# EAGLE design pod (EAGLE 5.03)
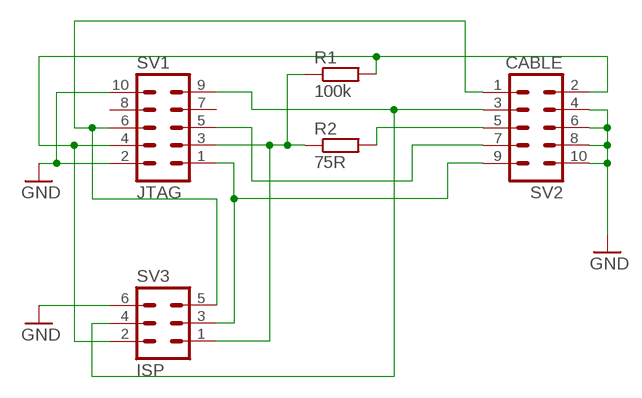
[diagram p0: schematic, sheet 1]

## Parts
R1  100k  R  [0207/10]
R2  75R  R  [0207/10]
SV1  JTAG  ML10L  [ML10L]
SV2  CABLE  ML10L  [ML10L]
SV3  ISP  ML6L  [ML6L]

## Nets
GND [supply]: SV1.2 SV1.10 SV2.4 SV2.6 SV2.8 SV2.10 SV3.6
N$1: R1.1 R2.1 SV1.3 SV3.1
N$2: R1.2 SV1.4 SV2.2 SV3.2
N$3: R2.2 SV2.5
N$4: SV1.6 SV2.1 SV3.5
N$5: SV1.9 SV2.3 SV3.4
N$6: SV1.5 SV2.7
N$7: SV1.1 SV2.9 SV3.3
Unconnected: SV1.7 SV1.8

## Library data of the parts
R1 R2 = ee2parts:R: Resistor
SV1 SV2 = con-ml:ML10L: HARTING
SV3 = con-ml:ML6L: HARTING

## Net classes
1 supply: width 2.54 mm

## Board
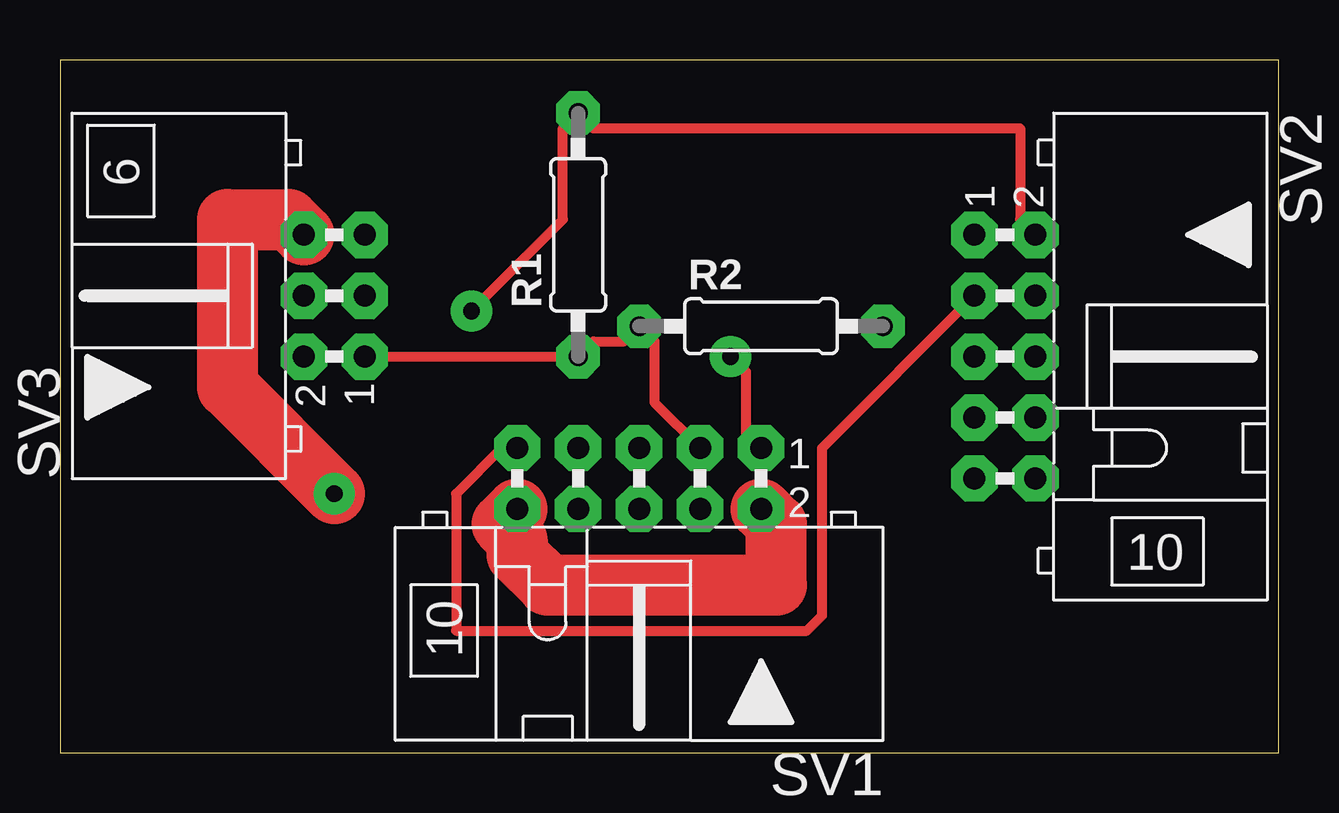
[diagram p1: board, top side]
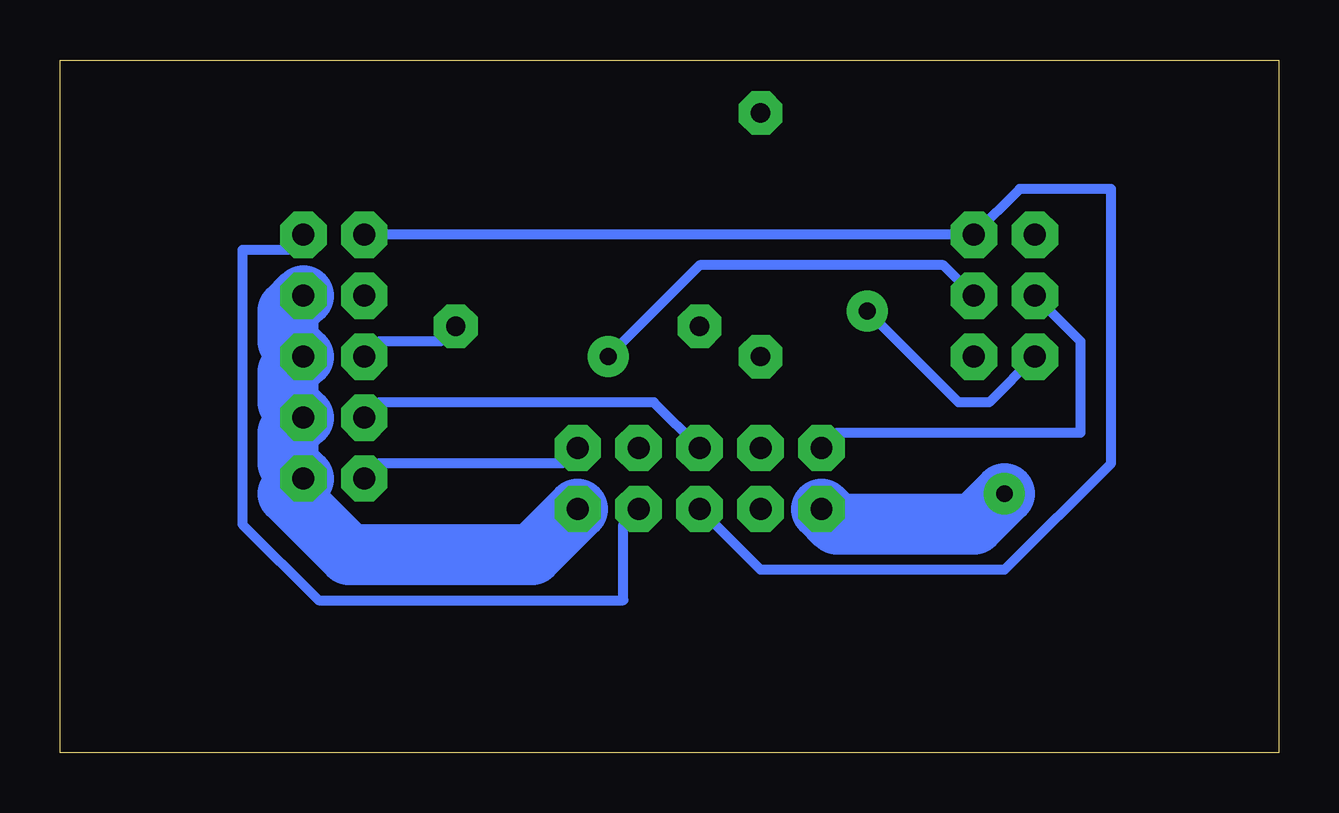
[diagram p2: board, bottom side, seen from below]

Size 50.78 x 28.88 mm. Coordinates in mm from the lower left corner, seen from the top.
Outline: 0,0 50.78,0 50.78,28.88 0,28.88 0,0
Copper layers (1*16): Top 0.035mm / dielectric 1.5mm / Bottom 0.035mm
Design rules "zigbit_rules": minimum track width 16mil, minimum drill 0.7mm, track to track 13mil, track to pad 13mil, pad to pad 13mil, via to via 13mil, smd to smd 0mil, copper to edge 10mil, drill to drill 10mil, minimum pad ring 20mil, minimum via ring 20mil, stop-mask expansion 0mil, vias tented up to drill 0mil, thermal gap 15mil
tRestrict: area 8.9,15.2 to 11.4,20.3; area 20.3,8.9 to 27.9,11.4; area 39.4,10.2 to 41.9,20.3
vRestrict: area 38.1,7.6 to 48.3,27.9; area 40.6,26.7 to 50.8,27.9; area 0,10.2 to 10.2,27.9; area 12.7,0 to 35.6,10.2

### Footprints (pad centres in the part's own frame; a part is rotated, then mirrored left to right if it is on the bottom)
0207/10 = drill 0.8 octagon: 1 -5.08,0; 2 5.08,0
ML10L = drill 0.914 octagon: 1 -5.08,-1.27; 2 -5.08,1.27; 3 -2.54,-1.27; 4 -2.54,1.27; 5 0,-1.27; 6 0,1.27; 7 2.54,-1.27; 8 2.54,1.27; 9 5.08,-1.27; 10 5.08,1.27
ML6L = drill 0.914 octagon: 1 -2.54,-1.27; 2 -2.54,1.27; 3 0,-1.27; 4 0,1.27; 5 2.54,-1.27; 6 2.54,1.27

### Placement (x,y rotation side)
R1  21.59,21.59 90 top
R2  29.21,17.78 0 top
SV1  24.13,11.43 180 top
SV2  39.37,16.51 270 top
SV3  11.43,19.05 90 top

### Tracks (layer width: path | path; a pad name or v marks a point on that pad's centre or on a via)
GND  (via drill 0.7)
  Top 2.54: SV1.10 18.41,9.53 19.05,8.89 19.05,8.25 20.32,6.99 29.84,6.99 29.84,9.53 SV1.2 | v11.43,10.8 6.99,15.24 6.99,22.22 9.53,22.22 SV3.6
  Bottom 2.54: SV2.4 41.27,18.41 41.27,17.14 SV2.6 41.27,15.88 41.27,14.61 SV2.8 41.27,13.34 41.27,12.07 SV2.10 41.27,10.8 38.73,8.25 31.12,8.25 SV1.2 | v11.43,10.8 12.7,9.53 18.41,9.53 SV1.10
N$1
  Top 0.406: SV3.1 R1.1 22.23,17.14 23.49,17.14 R2.1 24.77,17.14 24.77,14.61 SV1.3
N$2  (via drill 0.7)
  Top 0.406: SV2.2 40,22.22 40,26.04 22.23,26.04 R1.2 20.95,26.04 20.95,22.22 v17.15,18.41
  Bottom 0.406: v17.15,18.41 13.33,14.61 12.06,14.61 SV3.2 | SV1.4 27.3,9.53 27.3,6.35 40,6.35 43.18,9.53 43.18,20.95 41.27,20.95 SV2.2
N$3
  Bottom 0.406: R2.2 34.92,17.14 37.46,17.14 SV2.5
N$4
  Bottom 0.406: SV1.6 21.59,7.62 11.43,7.62 6.99,12.07 6.99,23.49 10.79,23.49 SV3.5 SV2.1
N$5
  Top 0.406: SV2.3 31.75,12.7 31.75,5.71 31.12,5.08 16.51,5.08 16.51,10.8 18.41,12.7 SV1.9
  Bottom 0.406: SV3.4 8.26,17.14 8.26,13.34 18.41,13.34 SV1.9
N$6
  Bottom 0.406: SV1.5 26.03,14.61 37.46,14.61 SV2.7
N$7  (via drill 0.7)
  Top 0.406: v27.94,16.51 28.57,15.88 28.57,13.34 SV1.1
  Bottom 0.406: v27.94,16.51 24.13,20.32 13.97,20.32 SV3.3 | SV2.9 37.46,12.07 29.84,12.07 SV1.1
